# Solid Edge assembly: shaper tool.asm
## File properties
Author: Deepak Maini
Template: Normal.asm
Last saved by: Robert a Rhodes jr
Revision: 30
Application: Solid Edge
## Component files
vertical slide.par
back plate.par
tool holder.par
spacer bush.par
washer.par
swivel plate.par
handle.par
screw bar.par
tool fixing screw.par
drag plate.par
small washer.par
clamping screw.par
pivot pin.par
handlear.par
nut.par
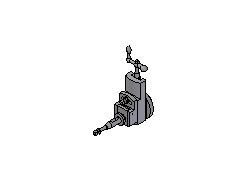
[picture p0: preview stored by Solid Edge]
